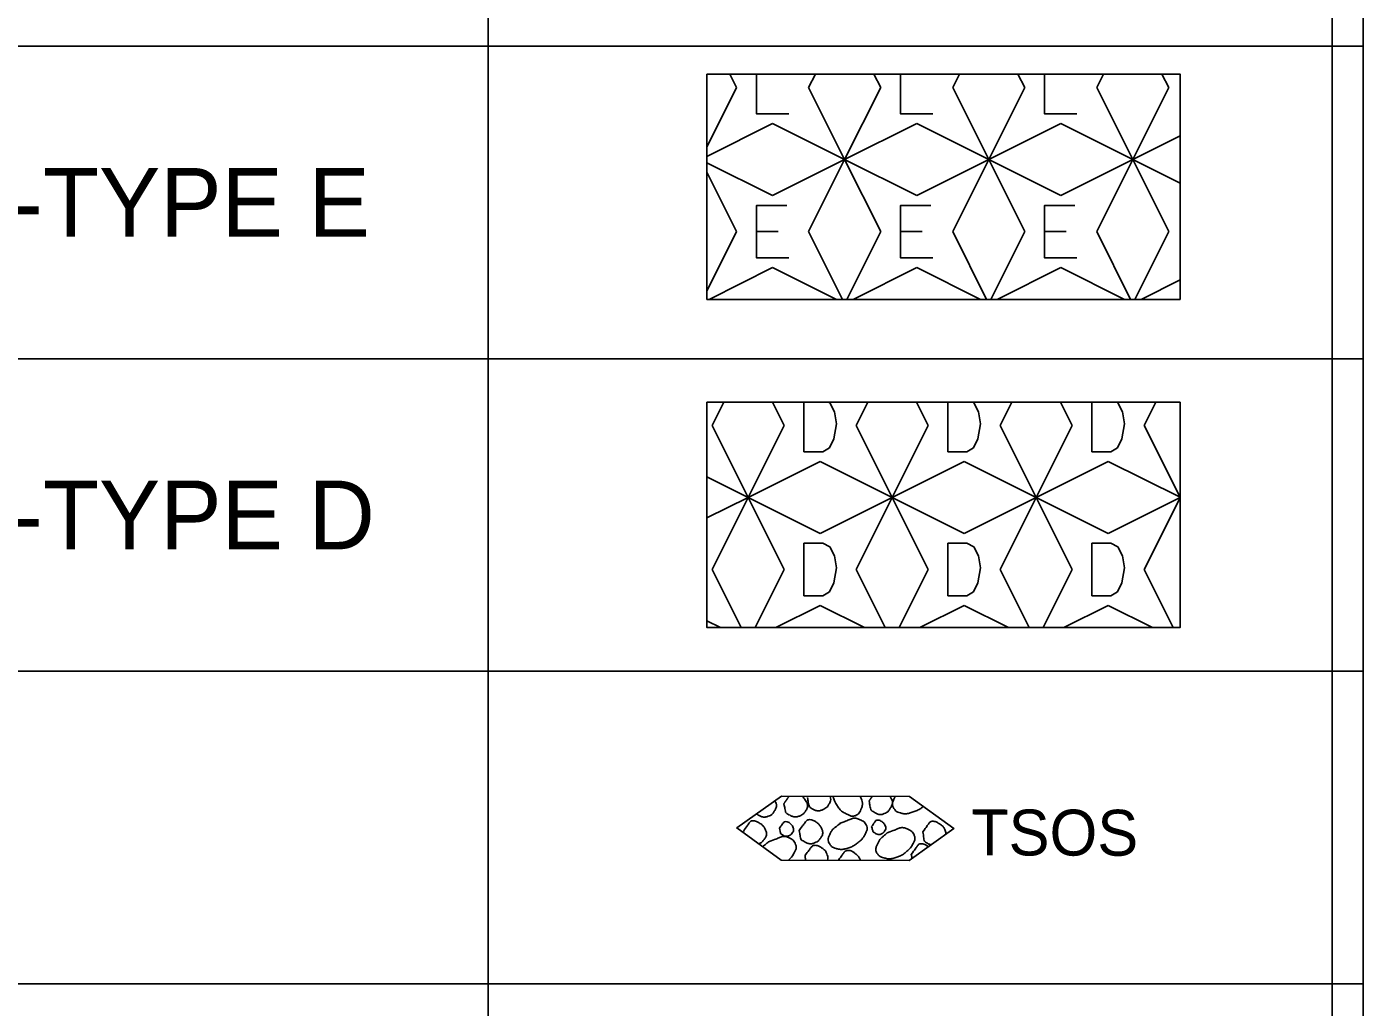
# Model space of a CAD drawing. Extents: x 1.3 to 34, y 0 to 22.5.
# Drawn here: x 16.062 to 18.2, y 11.287 to 12.856 of the extents above; entities that cross this region are included whole.
import ezdxf

# ---------------------------------------------------------------- set-up
doc = ezdxf.new("R2010")
doc.units = 0
for name, color, linetype in [('ANNO-SYMB', 7, 'Continuous'), ('ANNO-TABL', 7, 'Continuous'), ('USER-LINE', 7, 'Continuous')]:
    doc.layers.add(name, color=color, linetype=linetype)

msp = doc.modelspace()

# ---------------------------------------------------------------- linework, layer by layer
at = {"layer": 'ANNO-SYMB'}
for p, q in [((17.1975, 12.7587), (17.1867, 12.7803)), ((17.3235, 12.7803), (17.3127, 12.7587)), ((17.4279, 12.7587), (17.4171, 12.7803)), ((17.5539, 12.7803), (17.5431, 12.7587)), ((17.6583, 12.7587), (17.6475, 12.7803)), ((17.7843, 12.7803), (17.7735, 12.7587)), ((17.8887, 12.7587), (17.8779, 12.7803)), ((17.15, 12.6636), (17.1975, 12.7587)), ((17.3127, 12.7587), (17.3703, 12.6435)), ((17.3703, 12.6435), (17.4279, 12.7587)), ((17.5431, 12.7587), (17.6007, 12.6435)), ((17.6007, 12.6435), (17.6583, 12.7587)), ((17.7735, 12.7587), (17.8311, 12.6435)), ((17.8311, 12.6435), (17.8887, 12.7587)), ((17.2551, 12.7011), (17.15, 12.6485)), ((17.3703, 12.6435), (17.2551, 12.7011)), ((17.4855, 12.7011), (17.3703, 12.6435)), ((17.6007, 12.6435), (17.4855, 12.7011)), ((17.7159, 12.7011), (17.6007, 12.6435)), ((17.8311, 12.6435), (17.7159, 12.7011)), ((17.9068, 12.6813), (17.8311, 12.6435)), ((17.15, 12.6384), (17.2551, 12.5859)), ((17.2551, 12.5859), (17.3703, 12.6435)), ((17.3703, 12.6435), (17.3127, 12.5283)), ((17.3703, 12.6435), (17.4855, 12.5859)), ((17.4279, 12.5283), (17.3703, 12.6435)), ((17.4855, 12.5859), (17.6007, 12.6435)), ((17.6007, 12.6435), (17.5431, 12.5283)), ((17.6007, 12.6435), (17.7159, 12.5859)), ((17.6583, 12.5283), (17.6007, 12.6435)), ((17.7159, 12.5859), (17.8311, 12.6435)), ((17.8311, 12.6435), (17.7735, 12.5283)), ((17.8311, 12.6435), (17.9068, 12.6056)), ((17.8887, 12.5283), (17.8311, 12.6435)), ((17.1975, 12.5283), (17.15, 12.6233)), ((17.15, 12.4332), (17.1975, 12.5283)), ((17.2293, 12.5286), (17.2637, 12.5286)), ((17.3127, 12.5283), (17.367, 12.4197)), ((17.3737, 12.4197), (17.4279, 12.5283)), ((17.4597, 12.5286), (17.4941, 12.5286)), ((17.5431, 12.5283), (17.5974, 12.4197)), ((17.6041, 12.4197), (17.6583, 12.5283)), ((17.6901, 12.5286), (17.7245, 12.5286)), ((17.7735, 12.5283), (17.8278, 12.4197)), ((17.8345, 12.4197), (17.8887, 12.5283)), ((17.2551, 12.4707), (17.1533, 12.4197)), ((17.357, 12.4197), (17.2551, 12.4707)), ((17.4855, 12.4707), (17.3837, 12.4197)), ((17.5874, 12.4197), (17.4855, 12.4707)), ((17.7159, 12.4707), (17.6141, 12.4197)), ((17.8178, 12.4197), (17.7159, 12.4707)), ((17.9068, 12.4509), (17.8445, 12.4197)), ((17.1768, 12.2553), (17.1583, 12.2182)), ((17.2735, 12.2182), (17.255, 12.2553)), ((17.4072, 12.2553), (17.3887, 12.2182)), ((17.5039, 12.2182), (17.4854, 12.2553)), ((17.6376, 12.2553), (17.6191, 12.2182)), ((17.7343, 12.2182), (17.7158, 12.2553)), ((17.868, 12.2553), (17.8495, 12.2182)), ((17.1583, 12.2182), (17.2159, 12.103)), ((17.2159, 12.103), (17.2735, 12.2182)), ((17.3887, 12.2182), (17.4463, 12.103)), ((17.4463, 12.103), (17.5039, 12.2182)), ((17.6191, 12.2182), (17.6767, 12.103)), ((17.6767, 12.103), (17.7343, 12.2182)), ((17.8495, 12.2182), (17.9068, 12.1036)), ((17.3311, 12.1606), (17.2159, 12.103)), ((17.4463, 12.103), (17.3311, 12.1606)), ((17.5615, 12.1606), (17.4463, 12.103)), ((17.6767, 12.103), (17.5615, 12.1606)), ((17.7919, 12.1606), (17.6767, 12.103)), ((17.9068, 12.1032), (17.7919, 12.1606)), ((17.2159, 12.103), (17.15, 12.1359)), ((17.15, 12.0701), (17.2159, 12.103)), ((17.2159, 12.103), (17.1583, 11.9878)), ((17.2159, 12.103), (17.3311, 12.0454)), ((17.2735, 11.9878), (17.2159, 12.103)), ((17.3311, 12.0454), (17.4463, 12.103)), ((17.4463, 12.103), (17.3887, 11.9878)), ((17.4463, 12.103), (17.5615, 12.0454)), ((17.5039, 11.9878), (17.4463, 12.103)), ((17.5615, 12.0454), (17.6767, 12.103)), ((17.6767, 12.103), (17.6191, 11.9878)), ((17.6767, 12.103), (17.7919, 12.0454)), ((17.7343, 11.9878), (17.6767, 12.103)), ((17.7919, 12.0454), (17.9068, 12.1028)), ((17.9068, 12.1024), (17.8495, 11.9878)), ((17.1583, 11.9878), (17.2048, 11.8947)), ((17.227, 11.8947), (17.2735, 11.9878)), ((17.3887, 11.9878), (17.4352, 11.8947)), ((17.4574, 11.8947), (17.5039, 11.9878)), ((17.6191, 11.9878), (17.6656, 11.8947)), ((17.6878, 11.8947), (17.7343, 11.9878)), ((17.8495, 11.9878), (17.896, 11.8947)), ((17.3311, 11.9302), (17.2602, 11.8947)), ((17.402, 11.8947), (17.3311, 11.9302)), ((17.5615, 11.9302), (17.4906, 11.8947)), ((17.6324, 11.8947), (17.5615, 11.9302)), ((17.7919, 11.9302), (17.721, 11.8947)), ((17.8628, 11.8947), (17.7919, 11.9302)), ((17.1716, 11.8947), (17.15, 11.9055))]:
    msp.add_line(p, q, dxfattribs=at)
for points in [[(17.15, 12.7803), (17.9068, 12.7803), (17.9068, 12.4197), (17.15, 12.4197)], [(17.15, 12.2553), (17.9068, 12.2553), (17.9068, 11.8947), (17.15, 11.8947)], [(17.2691, 11.6251), (17.4739, 11.6246), (17.5452, 11.5732), (17.4737, 11.5221), (17.2688, 11.5227), (17.1976, 11.5741)]]:
    msp.add_lwpolyline(points, close=True, dxfattribs=at)
for points in [[(17.2293, 12.7803), (17.2293, 12.7167), (17.2809, 12.7167)], [(17.4597, 12.7803), (17.4597, 12.7167), (17.5113, 12.7167)], [(17.6901, 12.7803), (17.6901, 12.7167), (17.7417, 12.7167)], [(17.2776, 12.5703), (17.2293, 12.5703), (17.2293, 12.4863), (17.2809, 12.4863)], [(17.508, 12.5703), (17.4597, 12.5703), (17.4597, 12.4863), (17.5113, 12.4863)], [(17.7384, 12.5703), (17.6901, 12.5703), (17.6901, 12.4863), (17.7417, 12.4863)], [(17.3447, 12.2553), (17.3466, 12.2542), (17.3539, 12.2397), (17.3572, 12.2205), (17.3532, 12.1967), (17.346, 12.1821), (17.3354, 12.1762), (17.305, 12.1762), (17.305, 12.2553)], [(17.5751, 12.2553), (17.577, 12.2542), (17.5843, 12.2397), (17.5876, 12.2205), (17.5836, 12.1967), (17.5764, 12.1821), (17.5658, 12.1762), (17.5354, 12.1762), (17.5354, 12.2553)], [(17.8055, 12.2553), (17.8074, 12.2542), (17.8147, 12.2397), (17.818, 12.2205), (17.814, 12.1967), (17.8068, 12.1821), (17.7962, 12.1762), (17.7658, 12.1762), (17.7658, 12.2553)], [(17.305, 12.0298), (17.3354, 12.0298), (17.3466, 12.0238), (17.3539, 12.0093), (17.3572, 11.9901), (17.3532, 11.9663), (17.346, 11.9517), (17.3354, 11.9458), (17.305, 11.9458), (17.305, 12.0298)], [(17.5354, 12.0298), (17.5658, 12.0298), (17.577, 12.0238), (17.5843, 12.0093), (17.5876, 11.9901), (17.5836, 11.9663), (17.5764, 11.9517), (17.5658, 11.9458), (17.5354, 11.9458), (17.5354, 12.0298)], [(17.7658, 12.0298), (17.7962, 12.0298), (17.8074, 12.0238), (17.8147, 12.0093), (17.818, 11.9901), (17.814, 11.9663), (17.8068, 11.9517), (17.7962, 11.9458), (17.7658, 11.9458), (17.7658, 12.0298)]]:
    msp.add_lwpolyline(points, dxfattribs=at)
for points, degree in [([(17.2586, 11.6176), (17.2589, 11.6171), (17.2592, 11.6166), (17.2594, 11.616), (17.2617, 11.6114), (17.2607, 11.6055), (17.2576, 11.6006), (17.2552, 11.5967), (17.252, 11.5941), (17.2481, 11.5929), (17.2433, 11.5913), (17.2376, 11.5918), (17.2332, 11.5941), (17.2318, 11.5948), (17.2304, 11.5956), (17.2291, 11.5965)], 3), ([(17.2731, 11.613), (17.2759, 11.617), (17.2787, 11.6211), (17.2816, 11.6251)], 2), ([(17.3021, 11.625), (17.3049, 11.6226), (17.307, 11.6196), (17.3088, 11.6165), (17.3114, 11.6121), (17.3107, 11.6057), (17.3076, 11.601), (17.3051, 11.5973), (17.3019, 11.5948), (17.2981, 11.5933), (17.2932, 11.5915), (17.2874, 11.592), (17.2826, 11.5945), (17.2796, 11.5962), (17.2761, 11.5979), (17.2755, 11.6011), (17.2747, 11.6051), (17.2739, 11.609), (17.2731, 11.613)], 3), ([(17.347, 11.6249), (17.3485, 11.6205), (17.3473, 11.6155), (17.3445, 11.611), (17.3421, 11.6071), (17.3388, 11.605), (17.335, 11.6033), (17.3304, 11.6014), (17.3246, 11.6014), (17.3201, 11.604), (17.317, 11.6057), (17.3136, 11.6078), (17.313, 11.6111), (17.3122, 11.6151), (17.3114, 11.6191), (17.3106, 11.623)], 3), ([(17.3953, 11.6248), (17.396, 11.6229), (17.3968, 11.6211), (17.3975, 11.6192), (17.3994, 11.6142), (17.3984, 11.6084), (17.3962, 11.6032), (17.3948, 11.5996), (17.3924, 11.5968), (17.3891, 11.5949), (17.3849, 11.5925), (17.3795, 11.5934), (17.3754, 11.5955), (17.3696, 11.5985), (17.3638, 11.6018), (17.36, 11.6074), (17.3561, 11.6131), (17.3533, 11.6187), (17.3514, 11.6249)], 3), ([(17.4094, 11.6174), (17.4111, 11.6198), (17.4128, 11.6223), (17.4145, 11.6247)], 2), ([(17.4427, 11.6246), (17.4436, 11.6235), (17.4444, 11.6222), (17.4451, 11.6209), (17.4474, 11.6164), (17.4462, 11.6103), (17.4432, 11.6054), (17.4408, 11.6015), (17.4376, 11.5988), (17.4337, 11.5971), (17.4291, 11.5951), (17.4233, 11.5957), (17.4188, 11.5984), (17.4158, 11.6002), (17.4124, 11.6022), (17.4117, 11.6055), (17.4109, 11.6095), (17.4101, 11.6134), (17.4094, 11.6174)], 3), ([(17.4961, 11.6086), (17.4957, 11.6083), (17.4954, 11.608), (17.495, 11.6077), (17.4896, 11.6034), (17.483, 11.6011), (17.4765, 11.5988), (17.4711, 11.5969), (17.4649, 11.5967), (17.4593, 11.5982), (17.4552, 11.5993), (17.4516, 11.6015), (17.4492, 11.6054), (17.4465, 11.6097), (17.4468, 11.6149), (17.4486, 11.6191), (17.4494, 11.6209), (17.4502, 11.6228), (17.4511, 11.6246)], 3), ([(17.3623, 11.5813), (17.3682, 11.5836), (17.3742, 11.586), (17.3801, 11.5883), (17.3853, 11.5904), (17.3914, 11.589), (17.3968, 11.5865), (17.4002, 11.5849), (17.4028, 11.5826), (17.4045, 11.5794), (17.4067, 11.5752), (17.4061, 11.5697), (17.4039, 11.5657), (17.4008, 11.56), (17.3973, 11.5551), (17.3919, 11.5508), (17.3861, 11.5462), (17.3801, 11.5434), (17.3735, 11.5414), (17.368, 11.5397), (17.3618, 11.5397), (17.3562, 11.5414), (17.3525, 11.5425), (17.3493, 11.5445), (17.3467, 11.548), (17.3437, 11.5521), (17.3437, 11.5576), (17.3456, 11.5617), (17.3476, 11.5661), (17.35, 11.571), (17.3539, 11.5741), (17.3569, 11.5765), (17.3599, 11.5789), (17.3629, 11.5812)], 3), ([(17.2082, 11.5686), (17.2113, 11.5731), (17.2145, 11.5777), (17.2177, 11.5822), (17.2206, 11.5863), (17.2282, 11.5853), (17.2326, 11.5828), (17.2371, 11.5802), (17.2409, 11.5766), (17.2433, 11.572), (17.2457, 11.5673), (17.2453, 11.5608), (17.242, 11.5566), (17.2395, 11.5533), (17.2367, 11.5503), (17.233, 11.5485)], 3), ([(17.2659, 11.5738), (17.2679, 11.5765), (17.2699, 11.5793), (17.2719, 11.5821), (17.2737, 11.5847), (17.2786, 11.5844), (17.2814, 11.5827), (17.284, 11.5811), (17.286, 11.5788), (17.2873, 11.5761), (17.2887, 11.5732), (17.2887, 11.5694), (17.2867, 11.5666), (17.2851, 11.5643), (17.2831, 11.5628), (17.2807, 11.5618), (17.2779, 11.5607), (17.2745, 11.5609), (17.2718, 11.5625), (17.27, 11.5635), (17.2681, 11.5647), (17.2676, 11.5666), (17.2671, 11.569), (17.2665, 11.5714), (17.2659, 11.5738)], 3), ([(17.2974, 11.5701), (17.3008, 11.5747), (17.3042, 11.5792), (17.3075, 11.5838), (17.3105, 11.5878), (17.318, 11.5875), (17.3224, 11.5849), (17.327, 11.5823), (17.3308, 11.5783), (17.3331, 11.5736), (17.3354, 11.5689), (17.3351, 11.5628), (17.3319, 11.5581), (17.3293, 11.5545), (17.3262, 11.5519), (17.3223, 11.5504), (17.3175, 11.5486), (17.3116, 11.5491), (17.3069, 11.5517), (17.3039, 11.5533), (17.3004, 11.5551), (17.2997, 11.5582), (17.299, 11.5622), (17.2982, 11.5662), (17.2974, 11.5701)], 3), ([(17.4134, 11.5764), (17.4154, 11.5791), (17.4174, 11.5819), (17.4194, 11.5847), (17.4211, 11.5871), (17.4256, 11.5867), (17.4283, 11.5852), (17.4311, 11.5837), (17.4333, 11.5815), (17.4348, 11.5787), (17.4364, 11.5758), (17.4362, 11.572), (17.4342, 11.5692), (17.4326, 11.5669), (17.4306, 11.5652), (17.4283, 11.5644), (17.4255, 11.5634), (17.422, 11.5639), (17.4193, 11.5656), (17.4176, 11.5667), (17.4157, 11.5679), (17.4152, 11.5698), (17.4146, 11.572), (17.414, 11.5742), (17.4134, 11.5764)], 3), ([(17.4384, 11.5662), (17.4443, 11.5685), (17.4503, 11.5709), (17.4562, 11.5733), (17.4614, 11.5753), (17.4675, 11.574), (17.4729, 11.5714), (17.4763, 11.5699), (17.4788, 11.5675), (17.4806, 11.5643), (17.483, 11.5601), (17.4827, 11.5547), (17.4806, 11.5506), (17.4776, 11.545), (17.474, 11.54), (17.4686, 11.5358), (17.4627, 11.5311), (17.4568, 11.5283), (17.4502, 11.5263), (17.4447, 11.5246), (17.4385, 11.5248), (17.4329, 11.5263), (17.429, 11.5274), (17.4255, 11.5293), (17.4228, 11.5329), (17.4196, 11.5372), (17.4202, 11.543), (17.4223, 11.5472), (17.4243, 11.5514), (17.4264, 11.556), (17.43, 11.5591), (17.433, 11.5616), (17.436, 11.5642), (17.439, 11.5668)], 3), ([(17.4955, 11.5678), (17.4987, 11.5724), (17.5019, 11.5769), (17.505, 11.5815), (17.5079, 11.5855), (17.5156, 11.5846), (17.5199, 11.582), (17.5243, 11.5794), (17.5284, 11.5762), (17.5306, 11.5713), (17.5317, 11.5688), (17.5322, 11.5663), (17.5321, 11.5638)], 3), ([(17.239, 11.5442), (17.2394, 11.5446), (17.2398, 11.5449), (17.2402, 11.5453), (17.2432, 11.5477), (17.2462, 11.55), (17.2492, 11.5524)], 3), ([(17.2486, 11.5518), (17.2545, 11.5542), (17.2605, 11.5565), (17.2664, 11.5589), (17.2716, 11.561), (17.2777, 11.5602), (17.2831, 11.5577), (17.2866, 11.556), (17.2891, 11.5533), (17.2908, 11.5499), (17.2929, 11.5458), (17.2928, 11.5406), (17.2908, 11.5368), (17.288, 11.5317), (17.2848, 11.5265), (17.2804, 11.5226)], 3), ([(17.4769, 11.5316), (17.4801, 11.5361), (17.4833, 11.5407), (17.4865, 11.5452), (17.4895, 11.5495), (17.4976, 11.5484), (17.502, 11.5458), (17.5028, 11.5453), (17.5037, 11.5447), (17.5045, 11.5442)], 3), ([(17.5085, 11.547), (17.5071, 11.5474), (17.5057, 11.548), (17.5044, 11.5488), (17.5013, 11.5504), (17.4977, 11.5526), (17.4972, 11.5559), (17.4967, 11.5599), (17.4961, 11.5638), (17.4955, 11.5678)], 3), ([(17.3068, 11.5296), (17.31, 11.534), (17.3132, 11.5384), (17.3164, 11.5427), (17.3193, 11.5467), (17.3269, 11.5464), (17.3312, 11.5439), (17.3357, 11.5412), (17.3398, 11.5377), (17.3419, 11.5325), (17.3433, 11.5292), (17.3437, 11.5258), (17.343, 11.5225)], 3), ([(17.3079, 11.5226), (17.3075, 11.5249), (17.3072, 11.5273), (17.3068, 11.5296)], 2), ([(17.3604, 11.5224), (17.3632, 11.5264), (17.3659, 11.5303), (17.3687, 11.5342), (17.3717, 11.5385), (17.3799, 11.5383), (17.3842, 11.5354), (17.3884, 11.5325), (17.3927, 11.5289), (17.3948, 11.5241), (17.3951, 11.5235), (17.3953, 11.5229), (17.3955, 11.5223)], 3), ([(17.4782, 11.5253), (17.4778, 11.5274), (17.4774, 11.5295), (17.4769, 11.5316)], 2)]:
    msp.add_open_spline(points, degree=degree, dxfattribs=at)
at = {"layer": 'ANNO-TABL'}
for p, q in [((2, 12.825), (18.2, 12.825)), ((2, 12.325), (18.2, 12.325)), ((2, 11.825), (18.2, 11.825)), ((2, 11.325), (18.2, 11.325))]:
    msp.add_line(p, q, dxfattribs=at)
msp.add_lwpolyline([(12.8, 7.825), (18.2, 7.825), (18.2, 19.825), (12.8, 19.825)], close=True, dxfattribs=at)
at = {"layer": 'USER-LINE'}
for p, q in [((16.8, 12.825), (16.8, 13.325)), ((18.15, 12.825), (18.15, 13.325)), ((16.8, 12.825), (12.85, 12.825)), ((18.15, 12.825), (16.8, 12.825)), ((16.8, 12.325), (16.8, 12.825)), ((18.15, 12.325), (18.15, 12.825)), ((16.8, 12.325), (12.85, 12.325)), ((18.15, 12.325), (16.8, 12.325)), ((16.8, 11.825), (16.8, 12.325)), ((18.15, 11.825), (18.15, 12.325)), ((16.8, 11.825), (12.85, 11.825)), ((18.15, 11.825), (16.8, 11.825)), ((16.8, 11.325), (16.8, 11.825)), ((18.15, 11.325), (18.15, 11.825)), ((16.8, 11.325), (12.85, 11.325)), ((18.15, 11.325), (16.8, 11.325)), ((16.8, 10.825), (16.8, 11.325)), ((18.15, 10.825), (18.15, 11.325))]:
    msp.add_line(p, q, dxfattribs=at)

# ---------------------------------------------------------------- texts
at = {"layer": 'ANNO-SYMB'}
msp.add_text('TSOS', height=0.07344, rotation=359.8481, dxfattribs=at).set_placement((17.5725, 11.5304))
at = {"layer": 'ANNO-TABL'}
for s, p in [('TEMPORARY SOIL STABILIZATION MATTING-TYPE E', (12.9, 12.52)), ('TEMPORARY SOIL STABILIZATION MATTING-TYPE D', (12.9, 12.02))]:
    msp.add_text(s, height=0.11, dxfattribs=at).set_placement(p)

doc.saveas('drawing.dxf')
